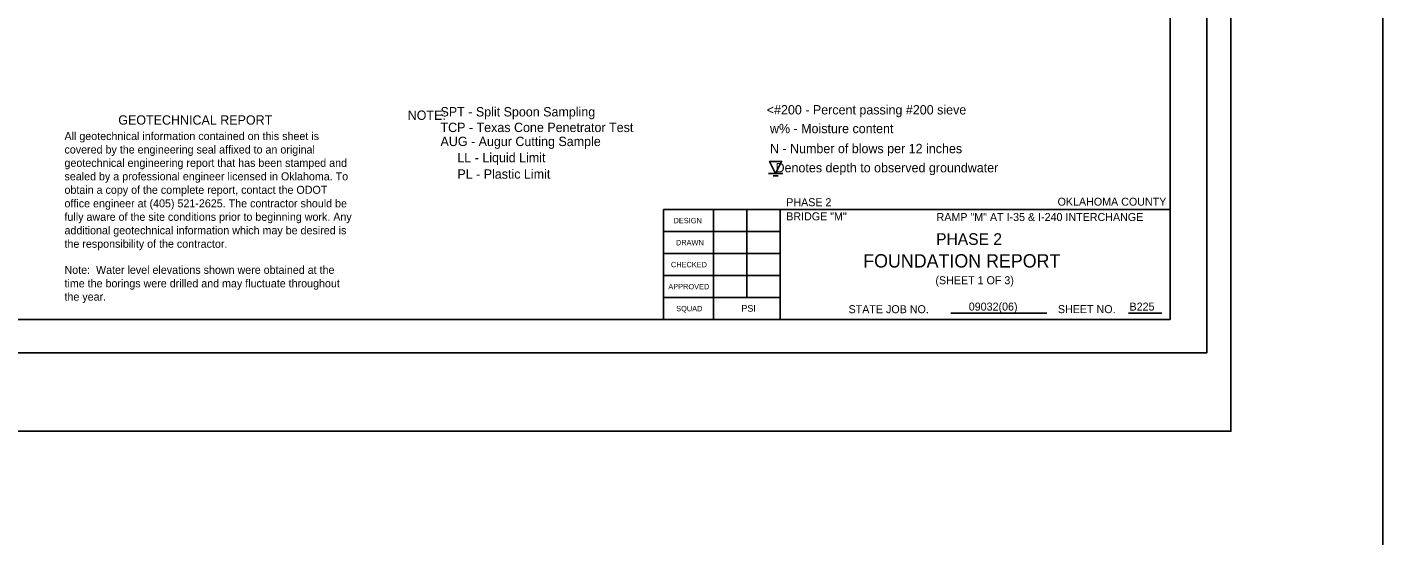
# Model space of a CAD drawing. Extents: x 2150161.5 to 2150203.1, y 143779.5 to 143868.5.
# Drawn here: x 2150182.73 to 2150203.07, y 143834.58 to 143842.21 of the extents above; entities that cross this region are included whole.
import ezdxf

# ---------------------------------------------------------------- set-up
doc = ezdxf.new("R2010")
doc.units = 0
for name, color, linetype in [('Default', 7, 'Continuous'), ('S', 7, 'Continuous'), ('SHT_Plot_Shape_Full', 7, 'Continuous'), ('SHT_Plot_Shape_Half', 7, 'Continuous'), ('SHT_Sheet_Border', 7, 'Continuous'), ('SHT_Standard_Sheet_Lines', 7, 'Continuous'), ('SHT_Standard_Sheet_Txt', 7, 'Continuous'), ('T', 7, 'Continuous'), ('T-Title', 7, 'Continuous'), ('Text', 7, 'Continuous')]:
    doc.layers.add(name, color=color, linetype=linetype)

# ---------------------------------------------------------------- blocks, each defined once
blk = doc.blocks.new('DGRFC_WTLEV1')
at = {"layer": 'Default'}
for points in [[(-0.0127, 0), (0.0127, 0)], [(0, 0), (0.0106, 0.0212), (-0.0106, 0.0212), (0, 0)], [(-0.0042, -0.0042), (0.0042, -0.0042)]]:
    blk.add_lwpolyline(points, dxfattribs=at)

msp = doc.modelspace()

# ---------------------------------------------------------------- linework, layer by layer
at = {"layer": 'S'}
msp.add_lwpolyline([(2150161.53, 143868.477), (2150203.071, 143868.477), (2150203.071, 143779.536), (2150161.53, 143779.536)], close=True, dxfattribs=at)
at = {"layer": 'SHT_Plot_Shape_Full'}
msp.add_lwpolyline([(2150164.792, 143860.145), (2150200.792, 143860.145), (2150200.792, 143836.145), (2150164.792, 143836.145)], close=True, dxfattribs=at)
at = {"layer": 'SHT_Plot_Shape_Half'}
msp.add_lwpolyline([(2150166.429, 143859.32), (2150200.429, 143859.32), (2150200.429, 143837.32), (2150166.429, 143837.32)], close=True, dxfattribs=at)
at = {"layer": 'SHT_Sheet_Border'}
for p, q in [((2150192.279, 143837.82), (2150192.279, 143839.47)), ((2150192.279, 143839.47), (2150199.879, 143839.47)), ((2150194.029, 143837.82), (2150194.029, 143839.471))]:
    msp.add_line(p, q, dxfattribs=at)
msp.add_lwpolyline([(2150199.879, 143837.82), (2150168.379, 143837.82), (2150168.379, 143858.82), (2150199.879, 143858.82)], close=True, dxfattribs=at)
at = {"layer": 'SHT_Standard_Sheet_Lines'}
for p, q in [((2150193.029, 143837.82), (2150193.029, 143839.471)), ((2150193.529, 143838.15), (2150193.529, 143839.471)), ((2150196.59, 143837.916), (2150198.03, 143837.917)), ((2150199.255, 143837.916), (2150199.757, 143837.917))]:
    msp.add_line(p, q, dxfattribs=at)
for points in [[(2150194.029, 143839.14), (2150192.279, 143839.14)], [(2150194.029, 143838.81), (2150192.279, 143838.81)], [(2150194.029, 143838.48), (2150192.279, 143838.48)], [(2150194.029, 143838.15), (2150192.279, 143838.15)]]:
    msp.add_lwpolyline(points, dxfattribs=at)

# ---------------------------------------------------------------- block references
at = {"layer": 'Default', "xscale": 8.503919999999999, "yscale": 8.503919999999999}
msp.add_blockref('DGRFC_WTLEV1', (2150193.962, 143840.011), dxfattribs=at)

# ---------------------------------------------------------------- texts
at = {"layer": 'Defpoints'}
msp.add_text('PHASE 2', height=0.175, dxfattribs=at).set_placement((2150196.369, 143838.94))
at = {"layer": 'SHT_Standard_Sheet_Txt'}
for s, height, p in [('DESIGN', 0.08, (2150192.431, 143839.265)), ('DRAWN', 0.08, (2150192.467, 143838.935)), ('CHECKED', 0.08, (2150192.392, 143838.605)), ('APPROVED', 0.08, (2150192.353, 143838.275)), ('STATE JOB NO.', 0.12, (2150195.056, 143837.916)), ('SHEET NO. ', 0.12, (2150198.196, 143837.917)), ('SQUAD', 0.08, (2150192.471, 143837.945))]:
    msp.add_text(s, height=height, dxfattribs=at).set_placement(p)
at = {"layer": 'T'}
for s, height, p in [('PHASE 2', 0.12, (2150194.121, 143839.52)), ('OKLAHOMA COUNTY', 0.12, (2150198.191, 143839.528)), ('BRIDGE "M"', 0.12, (2150194.121, 143839.308)), ('RAMP "M" AT I-35 & I-240 INTERCHANGE', 0.12, (2150196.376, 143839.298)), ('(SHEET 1 OF 3)', 0.12, (2150196.359, 143838.35)), ('PSI', 0.1, (2150193.449, 143837.938)), ('09032(06)', 0.12, (2150196.859, 143837.955)), ('B225', 0.12, (2150199.27, 143837.955))]:
    msp.add_text(s, height=height, dxfattribs=at).set_placement(p)
at = {"layer": 'T-Title'}
msp.add_text('FOUNDATION REPORT', height=0.2, dxfattribs=at).set_placement((2150195.276, 143838.601))
at = {"layer": 'Text'}
for s, height, p in [('GEOTECHNICAL REPORT', 0.14, (2150184.102, 143840.743)), ('NOTE:', 0.14, (2150188.443, 143840.815)), ('    SPT - Split Spoon Sampling', 0.14, (2150188.727, 143840.866)), (' <#200 - Percent passing #200 sieve', 0.14, (2150193.777, 143840.896)), ('    TCP - Texas Cone Penetrator Test', 0.14, (2150188.727, 143840.632)), ('w% - Moisture content', 0.14, (2150193.877, 143840.615)), ('All geotechnical information contained on this sheet is ', 0.12, (2150183.295, 143840.512)), ('    AUG - Augur Cutting Sample', 0.14, (2150188.727, 143840.422)), ('covered by the engineering seal affixed to an original ', 0.12, (2150183.295, 143840.31)), (' LL - Liquid Limit', 0.14, (2150189.136, 143840.179)), ('N - Number of blows per 12 inches', 0.14, (2150193.877, 143840.315)), ('geotechnical engineering report that has been stamped and ', 0.12, (2150183.295, 143840.11)), (' PL - Plastic Limit', 0.14, (2150189.136, 143839.933)), ('    Denotes depth to observed groundwater', 0.14, (2150193.753, 143840.028)), ('sealed by a professional engineer licensed in Oklahoma. To ', 0.12, (2150183.295, 143839.908)), ('obtain a copy of the complete report, contact the ODOT ', 0.12, (2150183.295, 143839.706)), ('office engineer at (405) 521-2625. The contractor should be ', 0.12, (2150183.295, 143839.503)), ('fully aware of the site conditions prior to beginning work. Any ', 0.12, (2150183.295, 143839.301)), ('additional geotechnical information which may be desired is ', 0.12, (2150183.295, 143839.099)), ('the responsibility of the contractor.', 0.12, (2150183.295, 143838.897)), ('Note:  Water level elevations shown were obtained at the ', 0.12, (2150183.295, 143838.506)), ('time the borings were drilled and may fluctuate throughout ', 0.12, (2150183.295, 143838.304)), ('the year.', 0.12, (2150183.295, 143838.104))]:
    msp.add_text(s, height=height, dxfattribs=at).set_placement(p)

doc.saveas('drawing.dxf')
